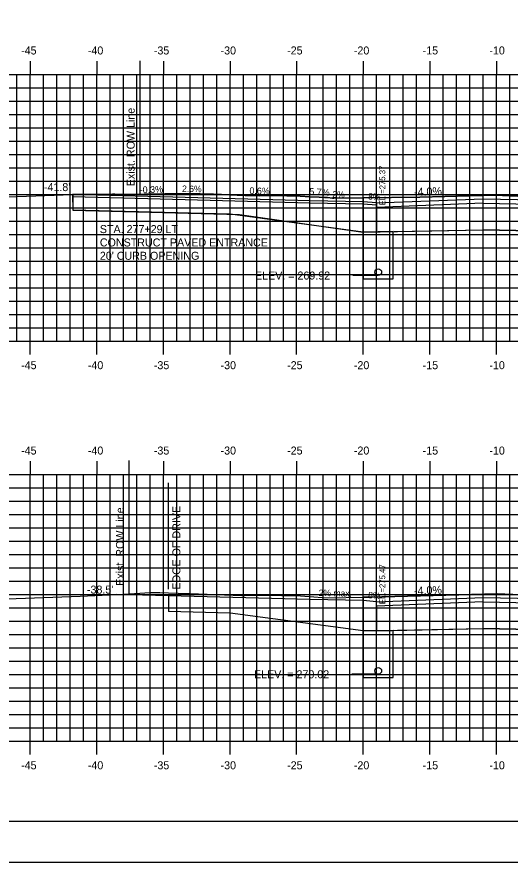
# Model space of a CAD drawing. Extents: x 854231 to 854401, y 366268 to 366378.
# Drawn here: x 854267.8 to 854304.8, y 366268.2 to 366331.6 of the extents above; entities that cross this region are included whole.
import ezdxf

# ---------------------------------------------------------------- set-up
doc = ezdxf.new("R2010")
doc.units = 0
for name, color, linetype in [('ANNOTATION', 7, 'Continuous'), ('BORDER', 7, 'Continuous'), ('D_Roadway_Drive_Gravel_LT', 7, 'Continuous'), ('D_Roadway_Drive_SubGrade', 7, 'Continuous'), ('D_Roadway_Edge_TW', 7, 'Continuous'), ('D_Roadway_FinishedGrade', 7, 'Continuous'), ('D_Roadway_SubGrade', 7, 'Continuous'), ('D_Text_Monospaced', 7, 'Continuous'), ('D_Text_Standard', 7, 'Continuous'), ('E_ROW_Line', 7, 'Continuous'), ('H_V ANNOTATION', 7, 'Continuous'), ('JUNK COM EXC', 7, 'Continuous'), ('junk strct exc', 7, 'Continuous'), ('MAJOR', 7, 'Continuous'), ('MINOR', 7, 'Continuous'), ('PDRAIN', 7, 'Continuous'), ('PLOT BOUNDARY', 7, 'Continuous'), ('S_Roadway_Centerline', 7, 'Continuous')]:
    doc.layers.add(name, color=color, linetype=linetype)

msp = doc.modelspace()

# ---------------------------------------------------------------- linework, layer by layer
at = {"layer": 'BORDER'}
msp.add_line((854238.771, 366271.236), (854398.771, 366271.236), dxfattribs=at)
at = {"layer": 'D_Roadway_Drive_Gravel_LT'}
for p, q in [((854289.774, 366317.762), (854271.971, 366318.224)), ((854289.77, 366317.595), (854271.971, 366318.058)), ((854293.766, 366317.515), (854289.771, 366317.595)), ((854293.774, 366317.682), (854289.774, 366317.762)), ((854294.774, 366317.602), (854293.774, 366317.682)), ((854294.774, 366317.602), (854294.774, 366317.268)), ((854283.771, 366316.751), (854271.971, 366317.057)), ((854294.771, 366317.435), (854293.766, 366317.515)), ((854289.774, 366287.863), (854275.266, 366288.24)), ((854293.774, 366287.783), (854289.774, 366287.863)), ((854289.774, 366287.863), (854289.774, 366287.863)), ((854294.774, 366287.703), (854293.774, 366287.783)), ((854283.771, 366286.852), (854279.14, 366286.973))]:
    msp.add_line(p, q, dxfattribs=at)
at = {"layer": 'D_Roadway_Drive_SubGrade'}
for p, q in [((854271.971, 366318.224), (854271.971, 366317.058)), ((854293.774, 366315.408), (854283.771, 366316.751)), ((854294.774, 366315.428), (854293.774, 366315.408)), ((854279.14, 366288.14), (854279.14, 366286.973)), ((854293.774, 366285.51), (854283.771, 366286.852)), ((854294.774, 366285.53), (854293.774, 366285.51))]:
    msp.add_line(p, q, dxfattribs=at)
at = {"layer": 'D_Roadway_Edge_TW'}
for points in [[(854294.774, 366317.602), (854302.774, 366317.922), (854324.774, 366317.482), (854332.77, 366317.161)], [(854294.774, 366287.703), (854302.774, 366288.023), (854324.774, 366287.583), (854332.77, 366287.263)]]:
    msp.add_lwpolyline(points, dxfattribs=at)
at = {"layer": 'D_Roadway_FinishedGrade'}
msp.add_line((854279.14, 366288.647), (854279.14, 366296.608), dxfattribs=at)
at = {"layer": 'D_Roadway_SubGrade'}
for points in [[(854302.774, 366317.588), (854294.774, 366317.268), (854294.774, 366315.428), (854302.774, 366315.588)], [(854302.774, 366315.588), (854302.774, 366317.588), (854313.774, 366317.368), (854324.774, 366317.148), (854324.774, 366315.148), (854313.774, 366315.368)], [(854302.774, 366287.69), (854294.774, 366287.37), (854294.774, 366285.53), (854302.774, 366285.69)], [(854302.774, 366285.69), (854302.774, 366287.69), (854313.774, 366287.47), (854324.774, 366287.25), (854324.774, 366285.25), (854313.774, 366285.47)]]:
    msp.add_lwpolyline(points, close=True, dxfattribs=at)
at = {"layer": 'D_Text_Standard'}
for points in [[(854294.899, 366312.158), (854293.663, 366312.158), (854292.983, 366312.158)], [(854294.899, 366282.26), (854293.603, 366282.26), (854292.923, 366282.26)]]:
    msp.add_lwpolyline(points, dxfattribs=at)
at = {"layer": 'E_ROW_Line'}
for p, q in [((854277.013, 366318.255), (854277.013, 366328.255)), ((854276.208, 366288.292), (854276.208, 366298.292))]:
    msp.add_line(p, q, dxfattribs=at)
at = {"layer": 'JUNK COM EXC'}
for points in [[(854293.771, 366315.409), (854293.771, 366317.983), (854291.571, 366317.952), (854291.457, 366317.96), (854291.08, 366318), (854290.854, 366318.017), (854290.462, 366318.038), (854289.754, 366318.052), (854289.034, 366318.1), (854288.47, 366318.13), (854288.033, 366318.124), (854286.911, 366318.16), (854285.976, 366318.146), (854284.911, 366318.153), (854282.528, 366318.252), (854282.033, 366318.256), (854281.52, 366318.273), (854280.425, 366318.286), (854279.184, 366318.279), (854278.884, 366318.285), (854275.782, 366318.236), (854275.425, 366318.244), (854275.116, 366318.253), (854274.938, 366318.258), (854271.957, 366318.224), (854271.971, 366317.057), (854284.488, 366316.732), (854293.771, 366315.409)], [(854333.77, 366316.851), (854327.6, 366317.07), (854323.667, 366317.268), (854314.957, 366317.71), (854311.743, 366317.84), (854303.643, 366318.188), (854298.019, 366318.041), (854293.772, 366317.983), (854293.774, 366315.408), (854302.774, 366315.588), (854324.774, 366315.148), (854333.774, 366314.968), (854333.77, 366316.851)], [(854293.772, 366288.043), (854293.774, 366285.51), (854302.774, 366285.69), (854324.774, 366285.25), (854333.774, 366285.07), (854333.77, 366286.951), (854332.973, 366286.981), (854327.686, 366287.169), (854318.367, 366287.641), (854314.902, 366287.816), (854313.222, 366287.894), (854303.833, 366288.299), (854294.211, 366288.049), (854293.772, 366288.043)]]:
    msp.add_lwpolyline(points, dxfattribs=at)
at = {"layer": 'junk strct exc'}
for points in [[(854293.774, 366315.408), (854293.774, 366311.908), (854296.024, 366311.908), (854296.024, 366315.453)], [(854293.774, 366285.51), (854293.774, 366282.01), (854296.024, 366282.01), (854296.024, 366285.555)]]:
    msp.add_lwpolyline(points, close=True, dxfattribs=at)
at = {"layer": 'MAJOR'}
for p, q in [((854268.771, 366328.238), (854268.771, 366327.236)), ((854273.771, 366328.238), (854273.771, 366327.236)), ((854278.771, 366328.238), (854278.771, 366327.236)), ((854283.771, 366328.238), (854283.771, 366327.236)), ((854288.771, 366328.238), (854288.771, 366327.236)), ((854293.771, 366328.238), (854293.771, 366327.236)), ((854298.771, 366328.238), (854298.771, 366327.236)), ((854303.771, 366328.238), (854303.771, 366327.236)), ((854243.771, 366327.236), (854383.771, 366327.236)), ((854243.771, 366327.236), (854383.771, 366327.236)), ((854268.771, 366307.236), (854268.771, 366327.236)), ((854273.771, 366307.236), (854273.771, 366327.236)), ((854278.771, 366307.236), (854278.771, 366327.236)), ((854283.771, 366307.236), (854283.771, 366327.236)), ((854288.771, 366307.236), (854288.771, 366327.236)), ((854293.771, 366307.236), (854293.771, 366327.236)), ((854298.771, 366307.236), (854298.771, 366327.236)), ((854303.771, 366307.236), (854303.771, 366327.236)), ((854243.771, 366322.236), (854383.771, 366322.236)), ((854243.771, 366317.236), (854383.771, 366317.236)), ((854243.771, 366312.236), (854383.771, 366312.236)), ((854243.771, 366307.236), (854383.771, 366307.236)), ((854243.771, 366307.236), (854383.771, 366307.236)), ((854268.771, 366306.234), (854268.771, 366307.236)), ((854273.771, 366306.234), (854273.771, 366307.236)), ((854278.771, 366306.234), (854278.771, 366307.236)), ((854283.771, 366306.234), (854283.771, 366307.236)), ((854288.771, 366306.234), (854288.771, 366307.236)), ((854293.771, 366306.234), (854293.771, 366307.236)), ((854298.771, 366306.234), (854298.771, 366307.236)), ((854303.771, 366306.234), (854303.771, 366307.236)), ((854268.771, 366298.238), (854268.771, 366297.236)), ((854273.771, 366298.238), (854273.771, 366297.236)), ((854278.771, 366298.238), (854278.771, 366297.236)), ((854283.771, 366298.238), (854283.771, 366297.236)), ((854288.771, 366298.238), (854288.771, 366297.236)), ((854293.771, 366298.238), (854293.771, 366297.236)), ((854298.771, 366298.238), (854298.771, 366297.236)), ((854303.771, 366298.238), (854303.771, 366297.236)), ((854243.771, 366297.236), (854383.771, 366297.236)), ((854243.771, 366297.236), (854383.771, 366297.236)), ((854268.771, 366277.236), (854268.771, 366297.236)), ((854273.771, 366277.236), (854273.771, 366297.236)), ((854278.771, 366277.236), (854278.771, 366297.236)), ((854283.771, 366277.236), (854283.771, 366297.236)), ((854288.771, 366277.236), (854288.771, 366297.236)), ((854293.771, 366277.236), (854293.771, 366297.236)), ((854298.771, 366277.236), (854298.771, 366297.236)), ((854303.771, 366277.236), (854303.771, 366297.236)), ((854243.771, 366292.236), (854383.771, 366292.236)), ((854243.771, 366287.236), (854383.771, 366287.236)), ((854243.771, 366282.236), (854383.771, 366282.236)), ((854243.771, 366277.236), (854383.771, 366277.236)), ((854243.771, 366277.236), (854383.771, 366277.236)), ((854268.771, 366276.234), (854268.771, 366277.236)), ((854273.771, 366276.234), (854273.771, 366277.236)), ((854278.771, 366276.234), (854278.771, 366277.236)), ((854283.771, 366276.234), (854283.771, 366277.236)), ((854288.771, 366276.234), (854288.771, 366277.236)), ((854293.771, 366276.234), (854293.771, 366277.236)), ((854298.771, 366276.234), (854298.771, 366277.236)), ((854303.771, 366276.234), (854303.771, 366277.236))]:
    msp.add_line(p, q, dxfattribs=at)
at = {"layer": 'MINOR'}
for p, q in [((854267.771, 366307.236), (854267.771, 366327.236)), ((854269.771, 366307.236), (854269.771, 366327.236)), ((854270.771, 366307.236), (854270.771, 366327.236)), ((854271.771, 366307.236), (854271.771, 366327.236)), ((854272.771, 366307.236), (854272.771, 366327.236)), ((854274.771, 366307.236), (854274.771, 366327.236)), ((854275.771, 366307.236), (854275.771, 366327.236)), ((854276.771, 366307.236), (854276.771, 366327.236)), ((854277.771, 366307.236), (854277.771, 366327.236)), ((854279.771, 366307.236), (854279.771, 366327.236)), ((854280.771, 366307.236), (854280.771, 366327.236)), ((854281.771, 366307.236), (854281.771, 366327.236)), ((854282.771, 366307.236), (854282.771, 366327.236)), ((854284.771, 366307.236), (854284.771, 366327.236)), ((854285.771, 366307.236), (854285.771, 366327.236)), ((854286.771, 366307.236), (854286.771, 366327.236)), ((854287.771, 366307.236), (854287.771, 366327.236)), ((854289.771, 366307.236), (854289.771, 366327.236)), ((854290.771, 366307.236), (854290.771, 366327.236)), ((854291.771, 366307.236), (854291.771, 366327.236)), ((854292.771, 366307.236), (854292.771, 366327.236)), ((854294.771, 366307.236), (854294.771, 366327.236)), ((854295.771, 366307.236), (854295.771, 366327.236)), ((854296.771, 366307.236), (854296.771, 366327.236)), ((854297.771, 366307.236), (854297.771, 366327.236)), ((854299.771, 366307.236), (854299.771, 366327.236)), ((854300.771, 366307.236), (854300.771, 366327.236)), ((854301.771, 366307.236), (854301.771, 366327.236)), ((854302.771, 366307.236), (854302.771, 366327.236)), ((854304.771, 366307.236), (854304.771, 366327.236)), ((854243.771, 366326.236), (854383.771, 366326.236)), ((854243.771, 366325.236), (854383.771, 366325.236)), ((854243.771, 366324.236), (854383.771, 366324.236)), ((854243.771, 366323.236), (854383.771, 366323.236)), ((854243.771, 366321.236), (854383.771, 366321.236)), ((854243.771, 366320.236), (854383.771, 366320.236)), ((854243.771, 366319.236), (854383.771, 366319.236)), ((854243.771, 366318.236), (854383.771, 366318.236)), ((854243.771, 366316.236), (854383.771, 366316.236)), ((854243.771, 366315.236), (854383.771, 366315.236)), ((854243.771, 366314.236), (854383.771, 366314.236)), ((854243.771, 366313.236), (854383.771, 366313.236)), ((854243.771, 366311.236), (854383.771, 366311.236)), ((854243.771, 366310.236), (854383.771, 366310.236)), ((854243.771, 366309.236), (854383.771, 366309.236)), ((854243.771, 366308.236), (854383.771, 366308.236)), ((854269.771, 366277.236), (854269.771, 366297.236)), ((854270.771, 366277.236), (854270.771, 366297.236)), ((854271.771, 366277.236), (854271.771, 366297.236)), ((854272.771, 366277.236), (854272.771, 366297.236)), ((854274.771, 366277.236), (854274.771, 366297.236)), ((854275.771, 366277.236), (854275.771, 366297.236)), ((854276.771, 366277.236), (854276.771, 366297.236)), ((854277.771, 366277.236), (854277.771, 366297.236)), ((854279.771, 366277.236), (854279.771, 366297.236)), ((854280.771, 366277.236), (854280.771, 366297.236)), ((854281.771, 366277.236), (854281.771, 366297.236)), ((854282.771, 366277.236), (854282.771, 366297.236)), ((854284.771, 366277.236), (854284.771, 366297.236)), ((854285.771, 366277.236), (854285.771, 366297.236)), ((854286.771, 366277.236), (854286.771, 366297.236)), ((854287.771, 366277.236), (854287.771, 366297.236)), ((854289.771, 366277.236), (854289.771, 366297.236)), ((854290.771, 366277.236), (854290.771, 366297.236)), ((854291.771, 366277.236), (854291.771, 366297.236)), ((854292.771, 366277.236), (854292.771, 366297.236)), ((854294.771, 366277.236), (854294.771, 366297.236)), ((854295.771, 366277.236), (854295.771, 366297.236)), ((854296.771, 366277.236), (854296.771, 366297.236)), ((854297.771, 366277.236), (854297.771, 366297.236)), ((854299.771, 366277.236), (854299.771, 366297.236)), ((854300.771, 366277.236), (854300.771, 366297.236)), ((854301.771, 366277.236), (854301.771, 366297.236)), ((854302.771, 366277.236), (854302.771, 366297.236)), ((854304.771, 366277.236), (854304.771, 366297.236)), ((854243.771, 366296.236), (854383.771, 366296.236)), ((854243.771, 366295.236), (854383.771, 366295.236)), ((854243.771, 366294.236), (854383.771, 366294.236)), ((854243.771, 366293.236), (854383.771, 366293.236)), ((854243.771, 366291.236), (854383.771, 366291.236)), ((854243.771, 366290.236), (854383.771, 366290.236)), ((854243.771, 366289.236), (854383.771, 366289.236)), ((854243.771, 366288.236), (854383.771, 366288.236)), ((854243.771, 366286.236), (854383.771, 366286.236)), ((854243.771, 366285.236), (854383.771, 366285.236)), ((854243.771, 366284.236), (854383.771, 366284.236)), ((854243.771, 366283.236), (854383.771, 366283.236)), ((854243.771, 366281.236), (854383.771, 366281.236)), ((854243.771, 366280.236), (854383.771, 366280.236)), ((854243.771, 366279.236), (854383.771, 366279.236)), ((854243.771, 366278.236), (854383.771, 366278.236))]:
    msp.add_line(p, q, dxfattribs=at)
at = {"layer": 'PDRAIN'}
for points in [[(854293.774, 366315.408), (854293.774, 366311.908), (854296.024, 366311.908), (854296.024, 366315.408)], [(854293.774, 366285.51), (854293.774, 366282.01), (854296.024, 366282.01), (854296.024, 366285.51)]]:
    msp.add_lwpolyline(points, dxfattribs=at)
for centre in [(854294.899, 366312.408), (854294.899, 366282.51)]:
    msp.add_circle(centre, 0.25, dxfattribs=at)
at = {"layer": 'PLOT BOUNDARY'}
msp.add_lwpolyline([(854230.678, 366268.177), (854400.678, 366268.177), (854400.678, 366378.177), (854230.678, 366378.177)], close=True, dxfattribs=at)
at = {"layer": 'S_Roadway_Centerline'}
for points in [[(854263.644, 366317.927), (854271.957, 366318.224), (854274.938, 366318.258), (854275.116, 366318.253), (854275.425, 366318.244), (854275.782, 366318.236), (854278.884, 366318.285), (854279.184, 366318.279), (854280.425, 366318.286), (854281.52, 366318.273), (854282.033, 366318.256), (854282.528, 366318.252), (854284.911, 366318.153), (854285.976, 366318.146), (854286.911, 366318.16), (854288.033, 366318.124), (854288.47, 366318.13), (854289.034, 366318.1), (854289.754, 366318.052), (854290.462, 366318.038), (854290.854, 366318.017), (854291.08, 366318), (854291.457, 366317.96), (854291.571, 366317.952), (854298.019, 366318.041), (854303.643, 366318.188), (854311.743, 366317.84)], [(854261.529, 366287.707), (854272.531, 366288.112), (854275.817, 366288.266), (854277.782, 366288.397), (854278.5, 366288.383), (854279.14, 366288.357), (854279.878, 366288.348), (854280.708, 366288.322), (854280.757, 366288.321), (854284.663, 366288.159), (854284.89, 366288.157), (854286.445, 366288.18), (854286.759, 366288.17), (854287.488, 366288.181), (854287.669, 366288.171), (854287.899, 366288.156), (854289.058, 366288.134), (854289.699, 366288.099), (854290.069, 366288.071), (854290.685, 366288.006), (854290.746, 366288.002), (854294.211, 366288.049), (854303.833, 366288.299), (854313.222, 366287.894)]]:
    msp.add_lwpolyline(points, dxfattribs=at)

# ---------------------------------------------------------------- texts
at = {"layer": 'ANNOTATION'}
for s, rotation, p in [('-4.0%', 2.29061, (854297.59, 366318.115)), ('EDGE OF DRIVE', 90, (854280.042, 366288.602)), ('-4.0%', 2.29061, (854297.59, 366288.217))]:
    msp.add_text(s, height=0.6, rotation=rotation, dxfattribs=at).set_placement(p)
for s, p in [('STA. 277+29 LT', (854273.999, 366315.341)), ('CONSTRUCT PAVED ENTRANCE', (854273.999, 366314.341)), ("20' CURB OPENING", (854273.999, 366313.341))]:
    msp.add_text(s, height=0.6, dxfattribs=at).set_placement(p)
at = {"layer": 'D_Roadway_Drive_Gravel_LT'}
for s, rotation, p in [('2.6%', 358.80778, (854280.167, 366318.433)), ('2%', 358.80778, (854291.445, 366318.01)), ('8%', 355.42608, (854294.12, 366317.869)), ('2% max.', 358.80778, (854290.42, 366288.133)), ('8%', 355.42608, (854294.12, 366287.971))]:
    msp.add_text(s, height=0.48, rotation=rotation, dxfattribs=at).set_placement(p)
at = {"layer": 'D_Text_Monospaced'}
for s, rotation, p in [('-0.3%', 1.73667, (854276.998, 366318.33)), ('0.6%', 358.65073, (854285.221, 366318.272)), ('5.7%', 356.51011, (854289.712, 366318.224))]:
    msp.add_text(s, height=0.5, rotation=rotation, dxfattribs=at).set_placement(p)
at = {"layer": 'D_Text_Standard'}
for s, p in [(' EL.=275.37', (854295.418, 366317.256)), (' EL.=275.47', (854295.418, 366287.358))]:
    msp.add_text(s, height=0.4335, rotation=90, dxfattribs=at).set_placement(p)
for s, p in [("-41.8'", (854269.8, 366318.489)), ('ELEV. = 269.92', (854285.642, 366311.858)), ("-38.5'", (854273.03, 366288.31)), ('ELEV. = 270.02', (854285.57, 366281.96))]:
    msp.add_text(s, height=0.6, dxfattribs=at).set_placement(p)
at = {"layer": 'E_ROW_Line'}
for p in [(854276.613, 366318.855), (854275.808, 366288.892)]:
    msp.add_text('Exist. ROW Line', height=0.6, rotation=90, dxfattribs=at).set_placement(p)
at = {"layer": 'H_V ANNOTATION'}
for s, p in [('-45', (854268.088, 366328.736)), ('-40', (854273.096, 366328.736)), ('-35', (854278.051, 366328.736)), ('-30', (854283.059, 366328.736)), ('-25', (854288.056, 366328.736)), ('-20', (854293.064, 366328.736)), ('-15', (854298.228, 366328.736)), ('-10', (854303.236, 366328.736)), ('-45', (854268.088, 366305.136)), ('-40', (854273.096, 366305.136)), ('-35', (854278.051, 366305.136)), ('-30', (854283.059, 366305.136)), ('-25', (854288.056, 366305.136)), ('-20', (854293.064, 366305.136)), ('-15', (854298.228, 366305.136)), ('-10', (854303.236, 366305.136)), ('-45', (854268.088, 366298.736)), ('-40', (854273.096, 366298.736)), ('-35', (854278.051, 366298.736)), ('-30', (854283.059, 366298.736)), ('-25', (854288.056, 366298.736)), ('-20', (854293.064, 366298.736)), ('-15', (854298.228, 366298.736)), ('-10', (854303.236, 366298.736)), ('-45', (854268.088, 366275.136)), ('-40', (854273.096, 366275.136)), ('-35', (854278.051, 366275.136)), ('-30', (854283.059, 366275.136)), ('-25', (854288.056, 366275.136)), ('-20', (854293.064, 366275.136)), ('-15', (854298.228, 366275.136)), ('-10', (854303.236, 366275.136))]:
    msp.add_text(s, height=0.6, dxfattribs=at).set_placement(p)

doc.saveas('drawing.dxf')
